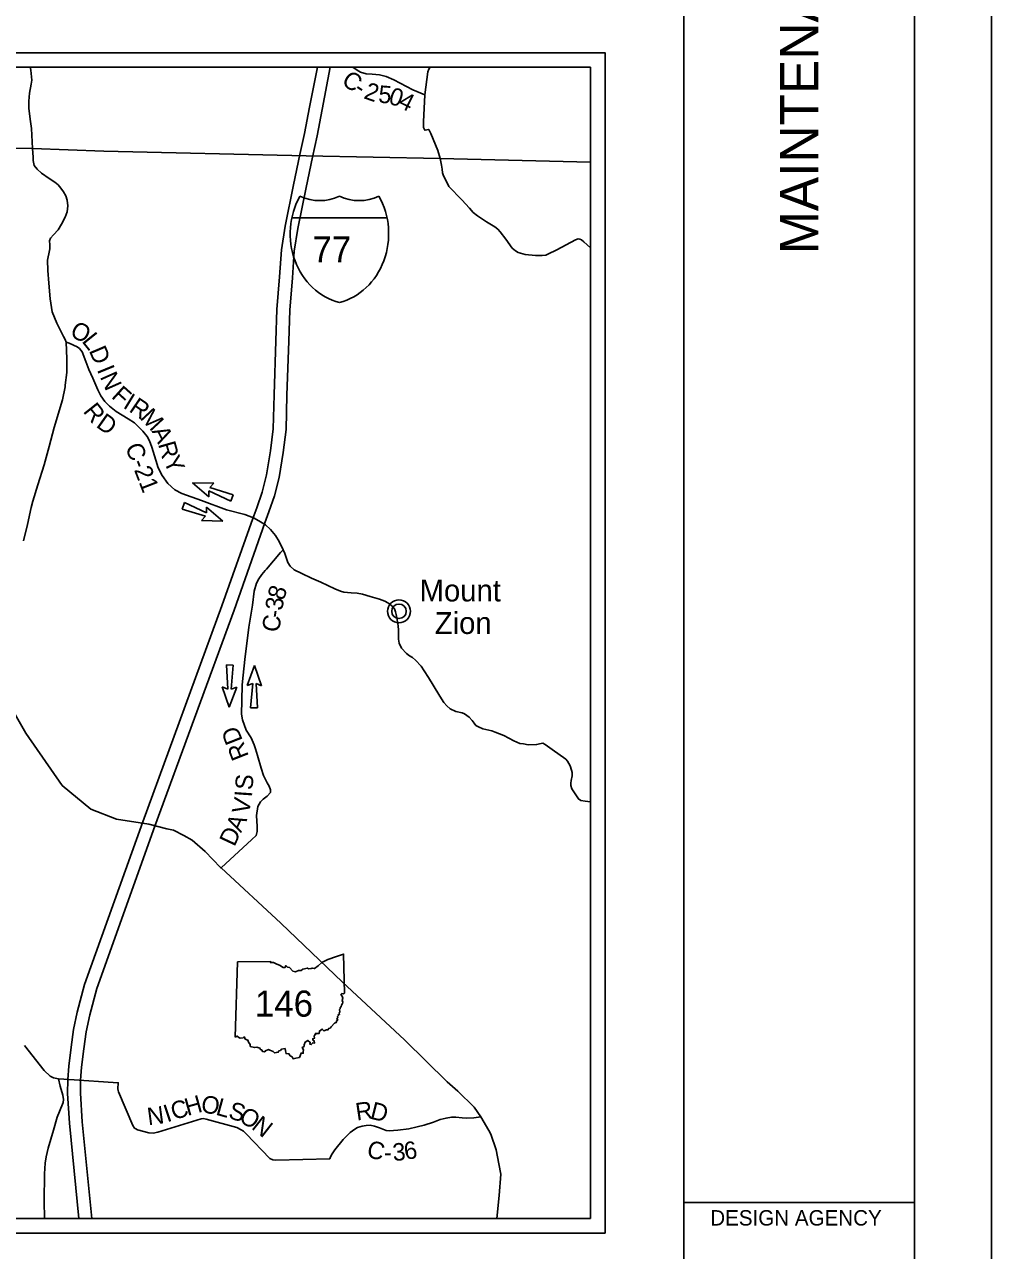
# Model space of a CAD drawing. Extents: x -452339 to 6403467, y -1 to 1814750.
# Drawn here: x -5560 to 27624, y 1587931 to 1629988 of the extents above; entities that cross this region are included whole.
import ezdxf

# ---------------------------------------------------------------- set-up
doc = ezdxf.new("R2010")
doc.units = 0
for name, color, linetype in [('Default', 7, 'Continuous'), ('GM_X_Adjacent_County_Text', 7, 'Continuous'), ('GM_X_Airport_Location_Class_2', 7, 'Continuous'), ('GM_X_County', 7, 'Continuous'), ('GM_X_County_Road', 7, 'Continuous'), ('GM_X_County_Road_Text', 7, 'Continuous'), ('GM_X_Interstate_Location', 7, 'Continuous'), ('GM_X_Minor_Lake_Text', 7, 'Continuous'), ('GM_X_Section_Text', 7, 'Continuous'), ('GM_X_State_Location', 7, 'Continuous')]:
    doc.layers.add(name, color=color, linetype=linetype)

msp = doc.modelspace()

# ---------------------------------------------------------------- linework, layer by layer
at = {"layer": 'Default'}
for p, q in [((-25629, 1628522), (13866, 1628522)), ((13866, 1628522), (13866, 1589027)), ((204, 1614268), (939, 1614250)), ((760, 1613787), (204, 1614268)), ((939, 1614250), (804, 1614100)), ((761, 1613990), (760, 1613787)), ((1515, 1613634), (761, 1613990)), ((804, 1614100), (1601, 1613855)), ((1601, 1613855), (1515, 1613634)), ((-151, 1613365), (-65, 1613586)), ((646, 1613119), (-151, 1613365)), ((-65, 1613586), (689, 1613231)), ((689, 1613231), (690, 1613433)), ((690, 1613433), (1246, 1612952)), ((510, 1612970), (646, 1613119)), ((1246, 1612952), (510, 1612970)), ((1414, 1607188), (1368, 1608020)), ((1368, 1608020), (1605, 1608016)), ((1605, 1608016), (1534, 1607185)), ((2080, 1607312), (2338, 1608001)), ((2338, 1608001), (2576, 1607305)), ((1465, 1606567), (1227, 1607263)), ((1227, 1607263), (1414, 1607188)), ((1723, 1607255), (1465, 1606567)), ((1534, 1607185), (1723, 1607255)), ((2270, 1607382), (2080, 1607312)), ((2199, 1606552), (2270, 1607382)), ((2576, 1607305), (2389, 1607380)), ((2389, 1607380), (2435, 1606548)), ((2435, 1606548), (2199, 1606552)), ((1664, 1595246), (1747, 1597828)), ((13866, 1589027), (-25629, 1589027))]:
    msp.add_line(p, q, dxfattribs=at)
msp.add_lwpolyline([(14366, 1588527), (-26129, 1588527), (-26129, 1629022), (14366, 1629022)], close=True, dxfattribs=at)
for points in [[(5705, 1628522), (5852, 1628422), (5975, 1628349), (6166, 1628299), (6369, 1628280), (6628, 1628257), (6847, 1628207), (7112, 1628095), (7770, 1627752), (8178, 1627578)], [(8709, 1625388), (8622, 1625668), (8386, 1626249), (8313, 1626392), (8181, 1626362), (8138, 1626455), (8132, 1626655), (8178, 1627578), (8276, 1628366), (8313, 1628461), (8365, 1628522)], [(13866, 1622323), (13640, 1622537), (13549, 1622602), (13497, 1622627), (13441, 1622631), (13345, 1622604), (12711, 1622262), (12398, 1622105), (12326, 1622078), (12210, 1622063), (11978, 1622061), (11619, 1622101), (11380, 1622163), (11285, 1622220), (11178, 1622321), (10958, 1622620), (10761, 1622874), (10682, 1622963), (10575, 1623052), (10297, 1623223), (9980, 1623426), (9841, 1623539), (9711, 1623689), (9447, 1623976), (9004, 1624428), (8804, 1624828), (8785, 1624902), (8773, 1625024), (8750, 1625161), (8709, 1625388)], [(-4132, 1619092), (-4033, 1619059), (-3755, 1618928), (-3675, 1618871), (-3581, 1618762), (-3460, 1618433), (-3351, 1618152), (-3210, 1617858), (-3043, 1617452), (-2937, 1617251), (-2803, 1617061), (-2645, 1616896), (-2412, 1616713), (-1999, 1616457), (-1785, 1616319), (-1654, 1616202), (-1496, 1616036), (-1350, 1615850), (-1276, 1615709), (-1190, 1615492), (-1059, 1615039), (-970, 1614782), (-841, 1614512), (-640, 1614238), (-399, 1614024), (-156, 1613905), (512, 1613662), (1375, 1613342), (1996, 1613180), (2155, 1613126), (2298, 1613060), (2484, 1612965), (2715, 1612828), (2881, 1612666), (3059, 1612457), (3184, 1612251), (3321, 1611970)], [(3321, 1611970), (3224, 1611870), (2740, 1611307), (2700, 1611261)], [(3321, 1611970), (3368, 1611841), (3426, 1611664), (3480, 1611536), (3559, 1611403), (3697, 1611285), (3956, 1611151), (4285, 1610995), (4611, 1610856), (5092, 1610631), (5283, 1610549), (5398, 1610520), (5650, 1610494), (5861, 1610480), (6040, 1610450), (6307, 1610371), (6618, 1610280), (6800, 1610202), (6908, 1610153), (6981, 1610106), (7053, 1610029), (7133, 1609943), (7166, 1609839), (7195, 1609745)], [(2700, 1611261), (2699, 1611259), (2582, 1611124), (2477, 1610973), (2399, 1610818), (2325, 1610554), (2268, 1610070), (2139, 1609309), (2006, 1608205), (1940, 1607663), (1909, 1607334), (1903, 1606798), (1891, 1606329), (1918, 1606133), (2044, 1605779), (2213, 1605513), (2321, 1605283), (2367, 1605136), (2435, 1604917), (2563, 1604478), (2639, 1604231), (2771, 1603969), (2841, 1603862), (2879, 1603739), (2877, 1603639), (2771, 1603517), (2625, 1603414), (2543, 1603324), (2445, 1603166), (2407, 1602853), (2429, 1602477), (2420, 1602309), (2395, 1602172), (2245, 1602025), (1184, 1601054)], [(7195, 1609745), (7221, 1609637), (7262, 1609365), (7280, 1609209), (7272, 1609005), (7270, 1608905), (7300, 1608761), (7379, 1608590), (7546, 1608413), (7656, 1608327), (7753, 1608269), (7854, 1608182), (8050, 1607974), (8160, 1607815), (8300, 1607590), (8469, 1607328), (8695, 1606952), (8835, 1606726), (8929, 1606619), (9047, 1606517), (9244, 1606425), (9465, 1606373), (9538, 1606338), (9696, 1606225), (9801, 1606110), (9871, 1606024), (9928, 1605945), (10017, 1605890), (10174, 1605829), (10479, 1605758), (10588, 1605716), (10886, 1605601), (11229, 1605415), (11439, 1605327), (11563, 1605313), (11720, 1605280), (12011, 1605285), (12175, 1605320), (12231, 1605329), (12311, 1605294), (12550, 1605122), (13012, 1604782), (13073, 1604719), (13160, 1604553), (13210, 1604413), (13236, 1604330), (13238, 1604218), (13201, 1604053), (13186, 1603964), (13192, 1603880), (13221, 1603765), (13451, 1603420), (13536, 1603366), (13681, 1603340), (13866, 1603325)], [(1747, 1597828), (2892, 1597845), (2874, 1597813), (2982, 1597807), (3097, 1597752), (3194, 1597717), (3312, 1597635), (3383, 1597636), (3413, 1597704), (3468, 1597651), (3532, 1597642), (3644, 1597518), (3737, 1597492), (3847, 1597534), (3929, 1597541), (3989, 1597583), (4146, 1597619), (4191, 1597597), (4274, 1597602), (4316, 1597617), (4389, 1597603), (4515, 1597698), (4647, 1597808), (4850, 1597913), (5151, 1598011), (5390, 1598100), (5425, 1596759)], [(5425, 1596759), (5390, 1596741), (5335, 1596750), (5298, 1596713), (5344, 1596650), (5365, 1596583), (5346, 1596511), (5365, 1596450), (5352, 1596400), (5318, 1596349), (5306, 1596302), (5276, 1596251), (5278, 1596223), (5251, 1596201), (5256, 1596117), (5242, 1596071), (5247, 1596031), (5201, 1596020), (5211, 1595987), (5183, 1595961), (5189, 1595917), (5156, 1595889), (5188, 1595833), (5162, 1595815), (5141, 1595747), (5083, 1595733), (4967, 1595608), (4926, 1595561), (4880, 1595549), (4854, 1595500), (4798, 1595500), (4711, 1595466), (4655, 1595524), (4558, 1595455), (4547, 1595374), (4424, 1595376), (4429, 1595336), (4401, 1595324), (4377, 1595283), (4391, 1595211), (4333, 1595192), (4340, 1595150), (4377, 1595125), (4393, 1595044), (4332, 1595060), (4282, 1594993), (4230, 1595009), (4247, 1595066), (4160, 1595136), (4077, 1595080), (4034, 1594991), (4034, 1594932), (3972, 1594896), (4012, 1594812), (4004, 1594754), (4006, 1594699), (3929, 1594701), (3882, 1594553)], [(3882, 1594553), (3749, 1594525), (3656, 1594508), (3623, 1594575), (3557, 1594611), (3513, 1594678), (3418, 1594687), (3396, 1594781), (3385, 1594856), (3255, 1594837), (3220, 1594791), (3173, 1594779), (3147, 1594732), (3083, 1594728), (3016, 1594706), (2971, 1594752), (2861, 1594798), (2811, 1594821), (2707, 1594785), (2685, 1594741), (2602, 1594760), (2583, 1594809), (2533, 1594824), (2521, 1594875), (2414, 1594903), (2332, 1594892), (2188, 1594933), (2179, 1595001), (2129, 1595083), (2105, 1595141), (2013, 1595184), (1994, 1595252), (1965, 1595250), (1939, 1595222), (1837, 1595210), (1796, 1595237), (1739, 1595285), (1664, 1595246)], [(-2329, 1593370), (-2329, 1593371), (-2351, 1593420), (-2359, 1593472), (-2344, 1593684), (-2512, 1593699), (-3856, 1593783), (-4392, 1593816), (-4561, 1593859), (-4681, 1593914), (-4886, 1594105), (-5564, 1594960)], [(-4876, 1589027), (-4883, 1589619), (-4869, 1590560), (-4856, 1590929), (-4821, 1591145), (-4751, 1591438), (-4568, 1592061), (-4443, 1592506), (-4361, 1592699), (-4239, 1593012), (-4219, 1593113), (-4241, 1593257), (-4331, 1593568), (-4392, 1593816)], [(10101, 1592518), (9855, 1592486), (9599, 1592472), (9455, 1592483), (9243, 1592505), (9091, 1592500), (8907, 1592475), (8699, 1592421), (8476, 1592335), (8157, 1592225), (7918, 1592175), (7626, 1592100), (7251, 1592053), (6955, 1592031), (6855, 1592046), (6626, 1592144), (6450, 1592199), (6298, 1592226), (6170, 1592221), (6022, 1592196), (5871, 1592151), (5771, 1592098), (5620, 1591984), (5374, 1591734), (5084, 1591383), (5001, 1591247), (4946, 1591146), (4915, 1591070), (3064, 1591027), (2964, 1591038), (2864, 1591082), (2050, 1591932), (1957, 1592024), (1873, 1592075), (1725, 1592146), (675, 1592438), (567, 1592453), (503, 1592445), (-981, 1591993), (-1149, 1591959), (-1293, 1591962), (-1681, 1592067), (-1734, 1592099), (-1783, 1592127), (-1846, 1592214), (-2329, 1593370)]]:
    msp.add_lwpolyline(points, dxfattribs=at)
for centre, major_axis, start_param, end_param in [((5738, 1622809), (0, -2422), 4.15077, 6.05619), ((4571, 1625878), (0, -1932), 5.88324, 6.683049), ((4757, 1622809), (0, -2422), 0.227007, 2.13242), ((5925, 1625879), (0, -1933), 5.883359, 6.683012)]:
    msp.add_ellipse(centre, major_axis=major_axis, ratio=0.9, start_param=start_param, end_param=end_param, dxfattribs=at)
at = {"layer": 'GM_X_Airport_Location_Class_2'}
msp.add_line((27624, 1565819), (27624, 1681979), dxfattribs=at)
at = {"layer": 'GM_X_County_Road'}
for points in [[(-5362, 1628522), (-5338, 1628425), (-5309, 1628078), (-5326, 1627947), (-5386, 1627636), (-5416, 1627355), (-5408, 1627120), (-5368, 1626739), (-5322, 1626418), (-5283, 1625736)], [(3892, 1625529), (4049, 1626255), (4225, 1627156), (4398, 1628065), (4496, 1628522)], [(4322, 1625436), (4480, 1626166), (4657, 1627072), (4933, 1628522)], [(-5283, 1625736), (-5267, 1625432), (-5261, 1625328), (-5254, 1625270), (-5243, 1625205), (-5223, 1625150), (-5123, 1625025), (-4974, 1624887), (-4715, 1624709), (-4517, 1624575), (-4406, 1624486), (-4315, 1624379), (-4226, 1624246), (-4145, 1624106), (-4092, 1623959), (-4070, 1623763), (-4101, 1623563), (-4168, 1623380), (-4293, 1623141), (-4410, 1622946), (-4564, 1622770), (-4667, 1622663), (-4702, 1622566), (-4693, 1622430), (-4696, 1622295), (-4727, 1622119), (-4752, 1622015), (-4774, 1621902), (-4755, 1621546), (-4721, 1621117), (-4677, 1620582), (-4615, 1620129), (-4447, 1619743), (-4355, 1619559), (-4222, 1619289), (-4163, 1619188), (-4132, 1619092), (-4106, 1618515), (-4102, 1618049), (-4161, 1617616), (-4162, 1617613)], [(-1497, 1602635), (1217, 1610050), (2276, 1613039), (2409, 1613412), (2593, 1613946), (2743, 1614543), (2884, 1615365), (2975, 1616123), (3005, 1617287), (3069, 1619139), (3102, 1620213), (3193, 1621328), (3256, 1622262), (3382, 1623067), (3670, 1624486), (3892, 1625528)], [(-1084, 1602484), (1631, 1609900), (2691, 1612892), (2824, 1613267), (3015, 1613820), (3174, 1614452), (3320, 1615301), (3414, 1616091), (3445, 1617274), (3509, 1619124), (3541, 1620189), (3632, 1621295), (3694, 1622213), (3815, 1622989), (4101, 1624397), (4322, 1625436)], [(-4162, 1617613), (-4169, 1617563), (-4259, 1617110), (-4540, 1616161), (-4712, 1615510), (-4885, 1614887), (-5105, 1614200), (-5271, 1613636), (-5335, 1613416), (-5452, 1612834), (-5598, 1612271)], [(-6152, 1606793), (-5517, 1605679), (-4266, 1603887), (-3284, 1603071), (-2398, 1602731), (-1291, 1602559), (-673, 1602397), (-447, 1602351), (-93, 1602171), (196, 1602005), (642, 1601615), (1169, 1601068), (1184, 1601054), (3240, 1599154), (5347, 1597139), (7482, 1595161), (7494, 1595149), (8950, 1593717), (9308, 1593399), (9868, 1592847), (10101, 1592518), (10373, 1592046), (10446, 1591918), (10625, 1591388), (10723, 1590903), (10785, 1590546), (10728, 1589816), (10650, 1589027)], [(-3691, 1589027), (-4018, 1592303), (-4081, 1593318), (-4076, 1593792), (-4043, 1594259), (-3962, 1594908), (-3877, 1595509), (-3748, 1596112), (-3502, 1597054), (-1498, 1602634)], [(-3249, 1589027), (-3579, 1592339), (-3641, 1593329), (-3636, 1593774), (-3605, 1594216), (-3526, 1594850), (-3443, 1595432), (-3320, 1596010), (-3081, 1596923), (-1084, 1602485)]]:
    msp.add_lwpolyline(points, dxfattribs=at)
at = {"layer": 'GM_X_County_Road_Text'}
for radius in [393, 249]:
    msp.add_circle((7291, 1609858), radius, dxfattribs=at)
at = {"layer": 'GM_X_Interstate_Location'}
for p, q in [((17064, 1568459), (17064, 1679339)), ((17064, 1589579), (24984, 1589579))]:
    msp.add_line(p, q, dxfattribs=at)
msp.add_lwpolyline([(-143976, 1679339), (24984, 1679339), (24984, 1568459), (-143976, 1568459)], close=True, dxfattribs=at)
at = {"layer": 'GM_X_Minor_Lake_Text'}
msp.add_line((3619, 1623353), (6881, 1623353), dxfattribs=at)
at = {"layer": 'GM_X_Section_Text'}
for p, q in [((-5283, 1625736), (-9874, 1625832)), ((-2840, 1625638), (-5283, 1625736)), ((4107, 1625482), (-2840, 1625638)), ((8709, 1625388), (4107, 1625482)), ((13866, 1625267), (8709, 1625388))]:
    msp.add_line(p, q, dxfattribs=at)

# ---------------------------------------------------------------- texts
at = {"layer": 'Default'}
for s, p in [('77', (4321, 1621826)), ('146', (2344, 1595953))]:
    msp.add_text(s, height=895.5, dxfattribs=at).set_placement(p)
at = {"layer": 'GM_X_Adjacent_County_Text'}
for s, p in [('Mount', (8000, 1610197)), ('Zion', (8520, 1609081))]:
    msp.add_text(s, height=750, rotation=0, dxfattribs=at).set_placement(p)
at = {"layer": 'GM_X_County'}
for s, rotation, p in [('C', 324.6048, (5283, 1627970)), ('-', 326.6535, (5704, 1627671)), ('2', 340.7081, (6053, 1627464)), ('5', 355.429, (6567, 1627308)), ('0', 341.895, (6898, 1627286)), ('4', 333.6142, (7228, 1627179)), ('O', 333.2183, (-4036, 1619314)), ('L', 308.7421, (-3617, 1619119)), ('D', 293.013, (-3359, 1618806)), ('I', 292.2949, (-3083, 1618151)), ('N', 294.0168, (-2982, 1617905)), ('F', 317.8384, (-2608, 1617203)), ('I', 328.6139, (-2209, 1616858)), ('R', 325.7882, (-2006, 1616734)), ('R', 308.5227, (-3572, 1616711)), ('M', 312.863, (-1625, 1616480)), ('D', 324.605, (-3134, 1616202)), ('A', 296.6433, (-1208, 1616040)), ('C-21', 291.1524, (-2113, 1615501)), ('R', 286.0151, (-982, 1615595)), ('Y', 295.5868, (-807, 1615019)), ('8', 72.1493, (3332, 1610204)), ('3', 82.7498, (3292, 1609866)), ('C', 80.5787, (3169, 1609112)), ('-', 80.9845, (3250, 1609602)), ('RD', 111.4284, (2149, 1604890)), ('S', 85.4814, (2262, 1603712)), ('I', 86.0564, (2245, 1603468)), ('V', 79.2362, (2137, 1602872)), ('D', 64.9811, (1643, 1601759)), ('A', 65.3128, (1868, 1602241)), ('H', 15.7673, (31, 1592542)), ('O', 350.1304, (469, 1592682)), ('L', 344.5261, (974, 1592595)), ('N', 7.6397, (-1311, 1592223)), ('I', 18.5685, (-666, 1592321)), ('C', 17.0944, (-436, 1592398)), ('S', 343.821, (1405, 1592476)), ('O', 329.9384, (1758, 1592378)), ('R', 8.3189, (5845, 1592385)), ('D', 346.0159, (6271, 1592460)), ('N', 321.8215, (2197, 1592126)), ('C', 345.1591, (6148, 1591151)), ('3', 5.0048, (7096, 1590998)), ('6', 9.4377, (7514, 1591036)), ('-', 358.2349, (6772, 1591003))]:
    msp.add_text(s, height=600, rotation=rotation, dxfattribs=at).set_placement(p)
at = {"layer": 'GM_X_State_Location'}
msp.add_text('MAINTENANCE OF TRAFFIC', height=1320, rotation=90, dxfattribs=at).set_placement((21684, 1622113))
msp.add_text('DESIGN AGENCY', height=528, dxfattribs=at).set_placement((17973, 1588787))

doc.saveas('drawing.dxf')
